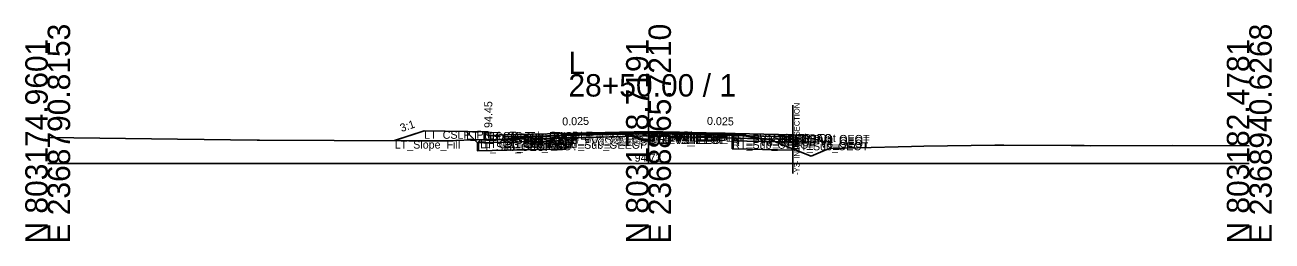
# Model space of a CAD drawing. Extents: x -26 to 8153, y -10 to 9520.
# Drawn here: x 1997.2 to 2152.8, y 990.3 to 1017.3 of the extents above; entities that cross this region are included whole.
import ezdxf

# ---------------------------------------------------------------- set-up
doc = ezdxf.new("R2010")
doc.units = 0
for name, color, linetype in [('Exist CMT Pavement', 7, 'Continuous'), ('Exist Cross Section Cell', 7, 'Continuous'), ('Exist XS Center Line Elevation Label', 7, 'Continuous'), ('Exist XS Ground Line', 7, 'Continuous'), ('Prop CMT Conc Surface', 7, 'Continuous'), ('Prop CMT Concrete Structures', 7, 'Continuous'), ('Prop CMT Pvmt Course 1', 7, 'Continuous'), ('Prop CMT Pvmt Course 1 CG', 7, 'Continuous'), ('Prop CMT Pvmt Course 1 Wedge', 7, 'Continuous'), ('Prop CMT Pvmt Course 2', 7, 'Continuous'), ('Prop CMT Pvmt Course 2 Wedge', 7, 'Continuous'), ('Prop CMT Pvmt Course 3', 7, 'Continuous'), ('Prop CMT Pvmt Course 3 Wedge', 7, 'Continuous'), ('Prop CMT Pvmt Surface', 7, 'Continuous'), ('Prop CMT Pvmt Wedge Surface 1', 7, 'Continuous'), ('Prop CMT Pvmt Wedge Surface 2', 7, 'Continuous'), ('Prop CMT Pvmt Wedge Surface 3', 7, 'Continuous'), ('Prop CMT Shallow Undercut', 7, 'Continuous'), ('Prop CMT Shallow Undercut Boundary', 7, 'Continuous'), ('Prop CMT Shear Line', 7, 'Continuous'), ('Prop CMT Slope Grass', 7, 'Continuous'), ('Prop CMT Subgrade Earthwork', 7, 'Continuous'), ('Prop XS Earthwork Shape', 7, 'Continuous'), ('Prop XS Hydro Elevations', 7, 'Continuous'), ('Prop XS SE Text', 7, 'Continuous'), ('Prop XS Side Slope Text', 7, 'Continuous'), ('Prop XS Subgrade Earthwork', 7, 'Continuous'), ('Scratch_Level_2', 7, 'Continuous'), ('Scratch_Level_6', 7, 'Continuous')]:
    doc.layers.add(name, color=color, linetype=linetype)

msp = doc.modelspace()

# ---------------------------------------------------------------- linework, layer by layer
at = {"layer": 'Exist CMT Pavement'}
for p, q in [((2064.66, 1003.56), (2065.05, 1003.56)), ((2065.05, 1003.56), (2075.04, 1003.73)), ((2075.04, 1003.73), (2077.53, 1003.72)), ((2077.53, 1003.72), (2079.56, 1003.71)), ((2079.56, 1003.71), (2085.45, 1003.69))]:
    msp.add_line(p, q, dxfattribs=at)
at = {"layer": 'Exist Cross Section Cell'}
for p, q in [((2075, 1000), (2075, 1011.18)), ((2000, 1000), (2075, 1000)), ((2075, 1000), (2150, 1000))]:
    msp.add_line(p, q, dxfattribs=at)
at = {"layer": 'Exist XS Ground Line'}
for p, q in [((2000, 1003.24), (2016.2, 1003.04)), ((2016.2, 1003.04), (2026.15, 1002.92)), ((2026.15, 1002.92), (2026.45, 1002.92)), ((2026.45, 1002.92), (2045.06, 1002.86)), ((2045.06, 1002.86), (2050.62, 1002.85)), ((2050.62, 1002.85), (2050.94, 1002.87)), ((2050.94, 1002.87), (2053, 1002.95)), ((2053, 1002.95), (2056.52, 1002.99)), ((2056.52, 1002.99), (2058.25, 1003.18)), ((2058.25, 1003.18), (2061.9, 1003.38)), ((2061.9, 1003.38), (2064.31, 1003.52)), ((2064.31, 1003.52), (2064.66, 1003.56)), ((2064.66, 1003.56), (2065.05, 1003.56)), ((2065.05, 1003.56), (2075.04, 1003.73)), ((2075.04, 1003.73), (2077.53, 1003.72)), ((2077.53, 1003.72), (2079.56, 1003.71)), ((2079.56, 1003.71), (2085.45, 1003.69)), ((2085.45, 1003.69), (2087.21, 1003.41)), ((2087.21, 1003.41), (2090.28, 1002.98)), ((2090.28, 1002.98), (2091.24, 1002.56)), ((2091.24, 1002.56), (2095.3, 1000.93)), ((2095.3, 1000.93), (2097.07, 1001.66)), ((2097.07, 1001.66), (2097.62, 1001.87)), ((2097.62, 1001.87), (2101.13, 1001.95)), ((2101.13, 1001.95), (2107.84, 1002.12)), ((2107.84, 1002.12), (2109.35, 1002.16)), ((2109.35, 1002.16), (2118.23, 1002.31)), ((2118.23, 1002.31), (2119.36, 1002.32)), ((2119.36, 1002.32), (2127.76, 1002.24)), ((2127.76, 1002.24), (2129.38, 1002.24)), ((2129.38, 1002.24), (2130.15, 1002.23)), ((2130.15, 1002.23), (2140.4, 1002.25)), ((2140.4, 1002.25), (2150, 1002.2))]:
    msp.add_line(p, q, dxfattribs=at)
at = {"layer": 'Prop CMT Conc Surface'}
for points in [[(2055, 1003.45), (2055, 1003.95), (2054.5, 1003.95)], [(2057, 1003.58), (2055, 1003.45)]]:
    msp.add_lwpolyline(points, dxfattribs=at)
at = {"layer": 'Prop CMT Concrete Structures'}
for points in [[(2057, 1003.58), (2055, 1003.45), (2055, 1003.95), (2054.5, 1003.95)], [(2054.5, 1003.95), (2054.5, 1002.93), (2057, 1002.99)], [(2057, 1002.99), (2057, 1003.58)]]:
    msp.add_lwpolyline(points, dxfattribs=at)
at = {"layer": 'Prop CMT Pvmt Course 1'}
for points in [[(2075, 1004.03), (2057, 1003.58)], [(2057, 1003.58), (2057, 1003.33)], [(2057, 1003.33), (2064.66, 1003.52)], [(2064.66, 1003.64), (2075, 1003.9)], [(2064.66, 1003.52), (2064.66, 1003.64)], [(2075, 1003.78), (2075, 1004.03)], [(2075, 1004.03), (2093, 1003.58)], [(2075, 1003.78), (2075, 1004.03)], [(2075, 1003.9), (2075, 1003.78), (2075, 1003.78)], [(2085.45, 1003.64), (2075, 1003.9)], [(2075, 1003.9), (2075, 1003.78), (2075, 1003.78)], [(2085.45, 1003.51), (2085.45, 1003.64)], [(2093, 1003.33), (2085.45, 1003.51)], [(2093, 1003.58), (2093, 1003.33)]]:
    msp.add_lwpolyline(points, dxfattribs=at)
at = {"layer": 'Prop CMT Pvmt Course 1 CG'}
for points in [[(2057, 1002.99), (2054, 1002.92), (2053.66, 1002.58)], [(2053.66, 1002.58), (2057, 1002.66)], [(2057, 1002.66), (2057, 1002.99)]]:
    msp.add_lwpolyline(points, dxfattribs=at)
at = {"layer": 'Prop CMT Pvmt Course 1 Wedge'}
for points in [[(2075, 1003.9), (2064.66, 1003.64)], [(2075, 1003.9), (2085.45, 1003.64)]]:
    msp.add_lwpolyline(points, dxfattribs=at)
at = {"layer": 'Prop CMT Pvmt Course 2'}
for points in [[(2064.66, 1003.52), (2057, 1003.33)], [(2057, 1003.33), (2057, 1003)], [(2057, 1003), (2064.66, 1003.19)], [(2064.66, 1003.19), (2064.66, 1003.52)], [(2085.45, 1003.18), (2085.45, 1003.51)], [(2085.45, 1003.51), (2093, 1003.33)], [(2093, 1003), (2085.45, 1003.18)], [(2093, 1003.33), (2093, 1003)]]:
    msp.add_lwpolyline(points, dxfattribs=at)
at = {"layer": 'Prop CMT Pvmt Course 2 Wedge'}
for points in [[(2075, 1003.78), (2064.66, 1003.52)], [(2075, 1003.78), (2085.45, 1003.51)]]:
    msp.add_lwpolyline(points, dxfattribs=at)
at = {"layer": 'Prop CMT Pvmt Course 3'}
for points in [[(2064.66, 1003.19), (2057, 1003)], [(2057, 1003), (2057, 1002.66)], [(2057, 1002.66), (2064.66, 1002.85)], [(2064.66, 1002.85), (2064.66, 1003.19)], [(2085.45, 1003.18), (2093, 1003)], [(2085.45, 1002.85), (2085.45, 1003.18)], [(2093, 1002.66), (2085.45, 1002.85)], [(2093, 1003), (2093, 1002.66)]]:
    msp.add_lwpolyline(points, dxfattribs=at)
at = {"layer": 'Prop CMT Pvmt Course 3 Wedge'}
for points in [[(2075, 1003.45), (2064.66, 1003.19)], [(2075, 1003.45), (2085.45, 1003.18)]]:
    msp.add_lwpolyline(points, dxfattribs=at)
at = {"layer": 'Prop CMT Pvmt Surface'}
for points in [[(2075, 1004.03), (2057, 1003.58)], [(2075, 1004.03), (2093, 1003.58), (2093, 1002.66)]]:
    msp.add_lwpolyline(points, dxfattribs=at)
at = {"layer": 'Prop CMT Pvmt Wedge Surface 1'}
for points in [[(2057, 1003.33), (2057, 1003.58)], [(2064.66, 1003.52), (2057, 1003.33)], [(2075, 1003.9), (2064.66, 1003.64)], [(2064.66, 1003.64), (2064.66, 1003.52)], [(2075, 1003.9), (2085.45, 1003.64)], [(2085.45, 1003.64), (2085.45, 1003.51)], [(2085.45, 1003.51), (2093, 1003.33)], [(2093, 1003.33), (2093, 1003.58)]]:
    msp.add_lwpolyline(points, dxfattribs=at)
at = {"layer": 'Prop CMT Pvmt Wedge Surface 2'}
for points in [[(2075, 1003.78), (2057, 1003.33)], [(2057, 1003.33), (2057, 1003.58)], [(2075, 1003.78), (2093, 1003.33)], [(2093, 1003.33), (2093, 1003.58)]]:
    msp.add_lwpolyline(points, dxfattribs=at)
at = {"layer": 'Prop CMT Pvmt Wedge Surface 3'}
for points in [[(2057, 1003), (2057, 1003.58)], [(2075, 1003.45), (2057, 1003)], [(2075, 1003.45), (2093, 1003)], [(2093, 1003), (2093, 1003.58)]]:
    msp.add_lwpolyline(points, dxfattribs=at)
at = {"layer": 'Prop CMT Shallow Undercut'}
for p, q in [((2064.66, 1002.85), (2053.66, 1002.58)), ((2064.66, 1001.85), (2064.66, 1002.85)), ((2053.66, 1002.58), (2053.66, 1001.58)), ((2053.66, 1001.58), (2064.66, 1001.85))]:
    msp.add_line(p, q, dxfattribs=at)
msp.add_lwpolyline([(2085.45, 1002.85), (2085.45, 1001.85), (2093, 1001.66), (2093, 1001.86), (2091.24, 1002.56), (2090.88, 1002.72)], close=True, dxfattribs=at)
at = {"layer": 'Prop CMT Shallow Undercut Boundary'}
for p, q in [((2053.66, 1002.58), (2064.66, 1002.85)), ((2064.66, 1002.85), (2064.66, 1001.85)), ((2085.45, 1002.85), (2085.45, 1001.85)), ((2085.45, 1002.85), (2093, 1002.66)), ((2093, 1002.66), (2093, 1001.66)), ((2053.66, 1002.58), (2053.66, 1001.58)), ((2064.66, 1001.85), (2053.66, 1001.58)), ((2085.45, 1001.85), (2093, 1001.66))]:
    msp.add_line(p, q, dxfattribs=at)
at = {"layer": 'Prop CMT Shear Line'}
msp.add_line((2093, 998.75), (2093, 1007.32), dxfattribs=at)
at = {"layer": 'Prop CMT Slope Grass'}
msp.add_lwpolyline([(2054.5, 1003.95), (2047, 1004.1), (2043.32, 1002.87)], dxfattribs=at)
at = {"layer": 'Prop CMT Subgrade Earthwork'}
for points in [[(2057, 1002.66), (2053.66, 1002.58), (2052.25, 1003.99)], [(2064.66, 1002.85), (2057, 1002.66)], [(2064.66, 1002.85), (2064.67, 1003.56)], [(2085.45, 1002.85), (2085.44, 1003.69)], [(2085.45, 1002.85), (2093, 1002.66)]]:
    msp.add_lwpolyline(points, dxfattribs=at)
at = {"layer": 'Prop XS Earthwork Shape'}
for points in [[(2050.62, 1002.85), (2050.94, 1002.87), (2053, 1002.95), (2053.29, 1002.95), (2052.25, 1003.99), (2047, 1004.1), (2043.31, 1002.87), (2045.06, 1002.86)], [(2064.31, 1003.52), (2064.66, 1003.56), (2064.67, 1003.56), (2064.66, 1002.85), (2057, 1002.66), (2053.66, 1002.58), (2053.29, 1002.95), (2056.52, 1002.99), (2058.25, 1003.18), (2061.9, 1003.38)], [(2064.66, 1001.85), (2053.66, 1001.58), (2053.66, 1002.58), (2057, 1002.66), (2064.66, 1002.85)], [(2085.45, 1002.85), (2090.88, 1002.72), (2090.28, 1002.98), (2087.21, 1003.41), (2085.45, 1003.69), (2085.44, 1003.69)], [(2085.45, 1002.85), (2090.88, 1002.72), (2091.24, 1002.56), (2093, 1001.86), (2093, 1001.66), (2085.45, 1001.85)], [(2091.24, 1002.56), (2093, 1001.86), (2093, 1002.66), (2090.88, 1002.72)]]:
    msp.add_lwpolyline(points, close=True, dxfattribs=at)
at = {"layer": 'Prop XS Subgrade Earthwork'}
for p, q in [((2053.66, 1002.58), (2064.66, 1002.85)), ((2093, 1002.66), (2085.45, 1002.85))]:
    msp.add_line(p, q, dxfattribs=at)
at = {"layer": 'Scratch_Level_6'}
for p, q in [((2064.66, 1002.85), (2053.66, 1002.58)), ((2064.66, 1001.85), (2064.66, 1002.85)), ((2053.66, 1002.58), (2053.66, 1001.58)), ((2053.66, 1001.58), (2064.66, 1001.85))]:
    msp.add_line(p, q, dxfattribs=at)
msp.add_lwpolyline([(2085.45, 1002.85), (2085.45, 1001.85), (2093, 1001.66), (2093, 1001.86), (2091.24, 1002.56), (2090.88, 1002.72)], close=True, dxfattribs=at)

# ---------------------------------------------------------------- texts
at = {"layer": 'Exist Cross Section Cell'}
for s, p in [('E 2368790.8153', (2002.8, 990)), ('E 2368865.7210', (2077.8, 990)), ('E 2368940.6268', (2152.8, 990)), ('N 803174.9601', (2000, 990)), ('N 803178.7191', (2075, 990)), ('N 803182.4781', (2150, 990))]:
    msp.add_text(s, height=2.8, rotation=90, dxfattribs=at).set_placement(p)
for s, p in [('L', (2065, 1011.18)), ('28+50.00 / 1', (2065, 1008.38))]:
    msp.add_text(s, height=2.8, dxfattribs=at).set_placement(p)
at = {"layer": 'Exist XS Center Line Elevation Label'}
msp.add_text('94.73', height=1, dxfattribs=at).set_placement((2073.27, 1000.23))
at = {"layer": 'Prop CMT Shear Line'}
msp.add_text('-Y3- INTERSECTION', height=0.7, rotation=90, dxfattribs=at).set_placement((2093.86, 998.59))
at = {"layer": 'Prop XS Hydro Elevations'}
msp.add_text('94.45', height=1, rotation=90, dxfattribs=at).set_placement((2055.5, 1004.45))
at = {"layer": 'Prop XS SE Text'}
for rotation, p in [(1.4321, (2064.24, 1004.76)), (358.5679, (2082.29, 1004.84))]:
    msp.add_text('0.025', height=1, rotation=rotation, dxfattribs=at).set_placement(p)
at = {"layer": 'Prop XS Side Slope Text'}
msp.add_text('3:1', height=1, rotation=18.4349, dxfattribs=at).set_placement((2044.17, 1003.94))
at = {"layer": 'Scratch_Level_2'}
for s, p in [('LT_Slope_Fill', (2043.32, 1001.87)), ('LT_CSLP_Pnt', (2047, 1003.1)), ('LT_Sub_Trench_Out_DLT', (2052.25, 1002.99)), ('LT_Sub_OEOP', (2053.66, 1001.58)), ('LT_CG1_Shelf_Out', (2054, 1001.92)), ('LT_CG_Top_BOC', (2054.5, 1002.95)), ('LT_CG_Bot_BOC', (2054.5, 1001.93)), ('LT_CG_Top_Face', (2055, 1002.95)), ('LT_CG_Top_Gut', (2055, 1002.45)), ('LT_PV1_OEOT', (2057, 1002.58)), ('LT_PV2_OEOT', (2057, 1002.33)), ('LT_PV3_OEOT', (2057, 1002)), ('LT_CG_Bot_IE', (2057, 1001.99)), ('LT_Sub_OEOT', (2057, 1001.66)), ('LT_PV1_OEEOP', (2064.66, 1002.64)), ('LT_PV_OEEOP_EG', (2064.66, 1002.56)), ('LT_PV2_OEEOP', (2064.66, 1002.52)), ('LT_PV3_OEEOP', (2064.66, 1002.19)), ('LT_Sub_OEEOP', (2064.66, 1001.85)), ('LT_PV_Sub_Tie_Out', (2064.67, 1002.56)), ('PV1_PGL', (2075, 1003.03)), ('RT_PV1_IEEOP', (2075, 1002.9)), ('LT_PV1_IEEOP', (2075, 1002.9)), ('RT_PV2_IEEOP', (2075, 1002.78)), ('LT_PV2_IEEOP', (2075, 1002.78)), ('PV2_PGL', (2075, 1002.78)), ('RT_PV_IEEOP_EG', (2075, 1002.73)), ('LT_PV_IEEOP_EG', (2075, 1002.73)), ('RT_PV3_IEEOP', (2075, 1002.45)), ('LT_PV3_IEEOP', (2075, 1002.45)), ('RT_PV_Sub_Tie_Out', (2085.44, 1002.69)), ('RT_PV_OEEOP_EG', (2085.45, 1002.69)), ('RT_PV1_OEEOP', (2085.45, 1002.64)), ('RT_PV2_OEEOP', (2085.45, 1002.51)), ('RT_PV3_OEEOP', (2085.45, 1002.18)), ('RT_Sub_OEEOP', (2085.45, 1001.85)), ('RT_PV1_OEOT', (2093, 1002.58)), ('RT_PV2_OEOT', (2093, 1002.33)), ('RT_PV3_OEOT', (2093, 1002)), ('RT_Sub_OEOT', (2093, 1001.66))]:
    msp.add_text(s, height=1, dxfattribs=at).set_placement(p)

doc.saveas('drawing.dxf')
